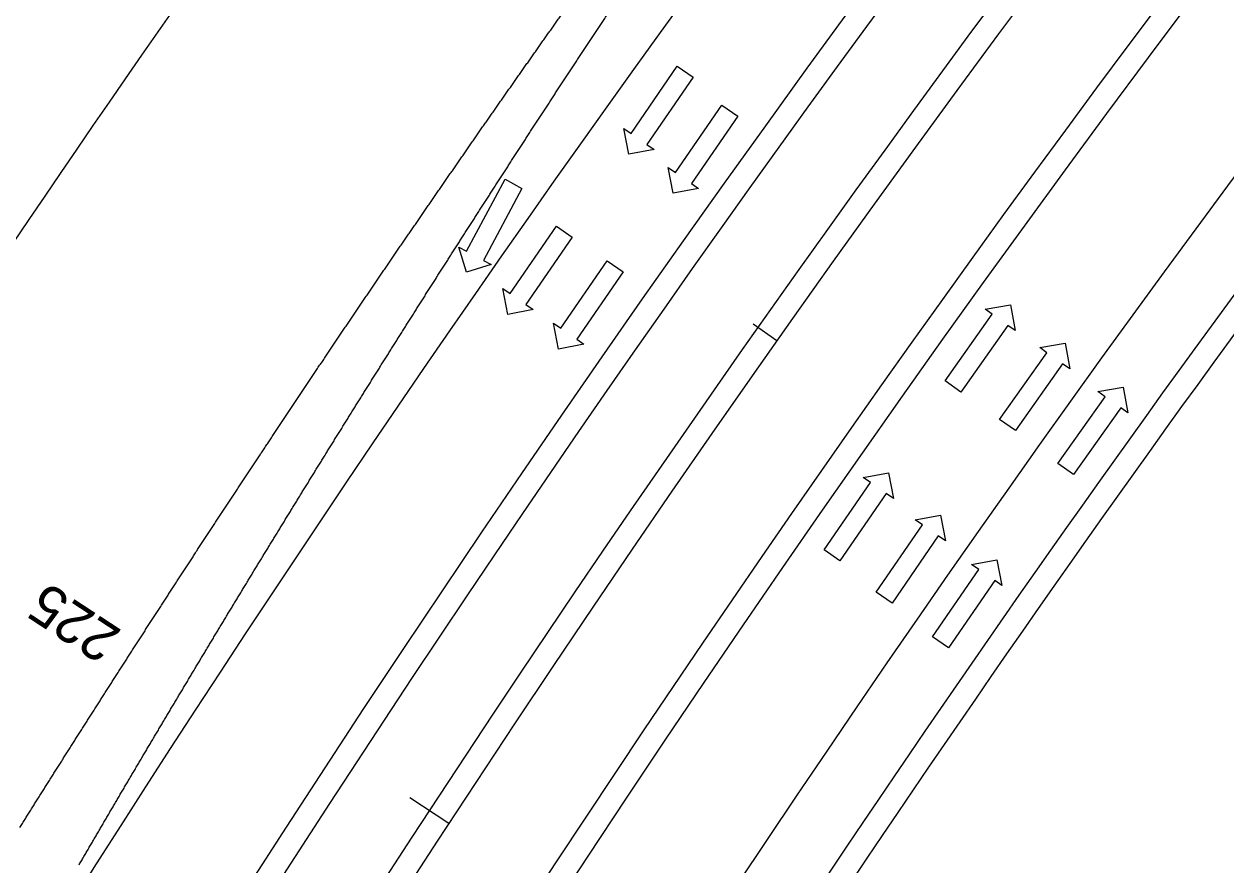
# Model space of a CAD drawing. Extents: x 2389694 to 2405615, y 547005 to 573532.
# Drawn here: x 2400552.8 to 2400758.8, y 569616.1 to 569760.3 of the extents above; entities that cross this region are included whole.
import ezdxf

# ---------------------------------------------------------------- set-up
doc = ezdxf.new("R2010")
doc.units = 0
for name, color, linetype in [('Prop Cable Guiderail Single Face', 7, 'Continuous'), ('Prop Dimension', 7, 'Continuous'), ('Prop EOT', 7, 'Continuous'), ('Prop Horizontal Alignment', 7, 'Continuous'), ('Prop Horizontal Alignment Curve and Spiral Data', 7, 'Continuous'), ('Prop Horizontal Alignment Tick Large', 7, 'Continuous'), ('Prop Horizontal Alignment Tick Small', 7, 'Continuous'), ('Prop Lane Arrow Through CELL', 7, 'Continuous'), ('Prop Lane Lines', 7, 'Continuous')]:
    doc.layers.add(name, color=color, linetype=linetype)

msp = doc.modelspace()

# ---------------------------------------------------------------- linework, layer by layer
at = {"layer": 'Prop Cable Guiderail Single Face'}
msp.add_arc((2403051.7, 568034.46), 2904, 119.41161, 162.0892, dxfattribs=at)
at = {"layer": 'Prop Dimension'}
msp.add_arc((2403051.7, 568034.46), 3017.28, 142.82813, 148.75528, dxfattribs=at)
at = {"layer": 'Prop EOT'}
for radius, start, end in [(2923, 119.41161, 180.94658), (2919, 119.41161, 162.43732), (2881, 119.41161, 165.38993), (2877, 119.41161, 180.94658), (2841, 142.65815, 148.75529), (2837, 142.65815, 148.75529)]:
    msp.add_arc((2403051.7, 568034.46), radius, start, end, dxfattribs=at)
for points in [[(2400619.32, 569725.07), (2400619.79, 569725.75), (2400620.26, 569726.44), (2400620.73, 569727.12), (2400621.2, 569727.8), (2400621.67, 569728.48), (2400622.13, 569729.16), (2400622.61, 569729.85), (2400623.08, 569730.53), (2400623.55, 569731.22), (2400624.02, 569731.9), (2400624.49, 569732.58), (2400624.96, 569733.26), (2400625.43, 569733.94), (2400625.9, 569734.62), (2400626.37, 569735.3), (2400626.84, 569735.98), (2400627.31, 569736.66), (2400627.78, 569737.34), (2400628.26, 569738.03), (2400628.73, 569738.71), (2400629.2, 569739.39), (2400629.67, 569740.07), (2400630.15, 569740.75), (2400630.62, 569741.43), (2400631.09, 569742.11), (2400631.56, 569742.79), (2400632.04, 569743.47), (2400632.51, 569744.15), (2400632.98, 569744.82), (2400633.46, 569745.5), (2400633.93, 569746.19), (2400634.41, 569746.87), (2400634.88, 569747.55), (2400635.36, 569748.22), (2400635.83, 569748.9), (2400636.31, 569749.58), (2400636.78, 569750.26), (2400637.26, 569750.94), (2400637.73, 569751.61), (2400638.21, 569752.29), (2400638.68, 569752.97), (2400639.16, 569753.64), (2400639.63, 569754.32), (2400640.11, 569755.01), (2400640.59, 569755.68), (2400641.07, 569756.36), (2400641.54, 569757.04), (2400642.02, 569757.71), (2400642.5, 569758.39), (2400642.98, 569759.06), (2400643.45, 569759.74), (2400643.93, 569760.42), (2400644.41, 569761.09), (2400644.89, 569761.77), (2400645.36, 569762.44), (2400645.85, 569763.13), (2400646.33, 569763.8), (2400646.81, 569764.48), (2400647.28, 569765.15), (2400647.76, 569765.83), (2400648.24, 569766.5), (2400648.72, 569767.17), (2400649.2, 569767.85), (2400649.68, 569768.52), (2400650.16, 569769.2), (2400650.64, 569769.87), (2400651.12, 569770.54), (2400651.61, 569771.23), (2400652.09, 569771.9), (2400652.57, 569772.57), (2400653.05, 569773.25), (2400653.53, 569773.92), (2400654.02, 569774.59), (2400654.5, 569775.27)], [(2400625.89, 569720.5), (2400626.34, 569721.2), (2400626.78, 569721.9), (2400627.23, 569722.59), (2400627.67, 569723.29), (2400628.12, 569723.98), (2400628.56, 569724.68), (2400629.01, 569725.38), (2400629.46, 569726.08), (2400629.91, 569726.77), (2400630.35, 569727.47), (2400630.8, 569728.16), (2400631.25, 569728.86), (2400631.69, 569729.55), (2400632.14, 569730.25), (2400632.59, 569730.94), (2400633.03, 569731.64), (2400633.48, 569732.33), (2400633.93, 569733.02), (2400634.38, 569733.73), (2400634.83, 569734.42), (2400635.28, 569735.11), (2400635.73, 569735.81), (2400636.18, 569736.5), (2400636.63, 569737.19), (2400637.08, 569737.89), (2400637.52, 569738.58), (2400637.97, 569739.27), (2400638.42, 569739.96), (2400638.87, 569740.66), (2400639.32, 569741.35), (2400639.78, 569742.05), (2400640.23, 569742.74), (2400640.68, 569743.44), (2400641.13, 569744.13), (2400641.58, 569744.82), (2400642.04, 569745.51), (2400642.49, 569746.2), (2400642.94, 569746.9), (2400643.39, 569747.59), (2400643.84, 569748.28), (2400644.29, 569748.97), (2400644.75, 569749.66), (2400645.2, 569750.35), (2400645.66, 569751.05), (2400646.11, 569751.74), (2400646.57, 569752.43), (2400647.02, 569753.12), (2400647.47, 569753.81), (2400647.93, 569754.5), (2400648.38, 569755.19), (2400648.84, 569755.88), (2400649.29, 569756.57), (2400649.74, 569757.26), (2400650.2, 569757.95), (2400650.65, 569758.64), (2400651.12, 569759.34), (2400651.57, 569760.03), (2400652.03, 569760.72), (2400652.48, 569761.41), (2400652.94, 569762.1), (2400653.4, 569762.79), (2400653.85, 569763.48), (2400654.31, 569764.16), (2400654.77, 569764.85), (2400655.22, 569765.54), (2400655.68, 569766.23), (2400656.14, 569766.92), (2400656.6, 569767.61), (2400657.06, 569768.3), (2400657.52, 569768.99), (2400657.98, 569769.68), (2400658.43, 569770.36), (2400658.89, 569771.05), (2400659.35, 569771.74)], [(2400585.2, 569674.17), (2400585.66, 569674.86), (2400586.11, 569675.55), (2400586.56, 569676.24), (2400587.02, 569676.93), (2400587.47, 569677.62), (2400587.93, 569678.31), (2400588.39, 569679.01), (2400588.84, 569679.71), (2400589.3, 569680.4), (2400589.75, 569681.09), (2400590.21, 569681.78), (2400590.66, 569682.47), (2400591.12, 569683.16), (2400591.58, 569683.85), (2400592.03, 569684.54), (2400592.49, 569685.23), (2400592.95, 569685.92), (2400593.4, 569686.61), (2400593.87, 569687.31), (2400594.32, 569688), (2400594.78, 569688.68), (2400595.24, 569689.37), (2400595.7, 569690.06), (2400596.15, 569690.75), (2400596.61, 569691.44), (2400597.07, 569692.13), (2400597.53, 569692.82), (2400597.99, 569693.51), (2400598.45, 569694.19), (2400598.91, 569694.88), (2400599.37, 569695.58), (2400599.83, 569696.27), (2400600.29, 569696.96), (2400600.75, 569697.64), (2400601.21, 569698.33), (2400601.67, 569699.02), (2400602.13, 569699.71), (2400602.59, 569700.39), (2400603.05, 569701.08), (2400603.51, 569701.77), (2400603.98, 569702.45), (2400604.44, 569703.14), (2400604.9, 569703.83), (2400605.37, 569704.52), (2400605.83, 569705.21), (2400606.29, 569705.89), (2400606.75, 569706.58), (2400607.22, 569707.27), (2400607.68, 569707.95), (2400608.14, 569708.64), (2400608.61, 569709.32), (2400609.07, 569710.01), (2400609.53, 569710.69), (2400610, 569711.38), (2400610.46, 569712.06), (2400610.93, 569712.76), (2400611.39, 569713.44), (2400611.86, 569714.13), (2400612.32, 569714.81), (2400612.79, 569715.49), (2400613.25, 569716.18), (2400613.72, 569716.86), (2400614.18, 569717.55), (2400614.65, 569718.23), (2400615.12, 569718.91), (2400615.58, 569719.6), (2400616.05, 569720.28), (2400616.52, 569720.97), (2400616.99, 569721.66), (2400617.45, 569722.34), (2400617.92, 569723.02), (2400618.39, 569723.71), (2400618.86, 569724.39), (2400619.32, 569725.07)], [(2400593.53, 569668.63), (2400593.96, 569669.33), (2400594.39, 569670.04), (2400594.82, 569670.74), (2400595.25, 569671.45), (2400595.68, 569672.15), (2400596.11, 569672.85), (2400596.55, 569673.57), (2400596.98, 569674.27), (2400597.41, 569674.97), (2400597.84, 569675.68), (2400598.27, 569676.38), (2400598.7, 569677.08), (2400599.14, 569677.79), (2400599.57, 569678.49), (2400600, 569679.19), (2400600.43, 569679.9), (2400600.87, 569680.6), (2400601.3, 569681.3), (2400601.74, 569682.01), (2400602.17, 569682.71), (2400602.6, 569683.42), (2400603.04, 569684.12), (2400603.47, 569684.82), (2400603.91, 569685.52), (2400604.34, 569686.22), (2400604.77, 569686.93), (2400605.21, 569687.63), (2400605.64, 569688.33), (2400606.08, 569689.03), (2400606.52, 569689.73), (2400606.96, 569690.44), (2400607.39, 569691.14), (2400607.83, 569691.84), (2400608.26, 569692.54), (2400608.7, 569693.24), (2400609.14, 569693.95), (2400609.57, 569694.65), (2400610.01, 569695.35), (2400610.45, 569696.05), (2400610.89, 569696.75), (2400611.32, 569697.45), (2400611.76, 569698.15), (2400612.2, 569698.85), (2400612.64, 569699.55), (2400613.08, 569700.25), (2400613.52, 569700.95), (2400613.96, 569701.65), (2400614.4, 569702.35), (2400614.84, 569703.05), (2400615.28, 569703.75), (2400615.72, 569704.45), (2400616.16, 569705.15), (2400616.6, 569705.84), (2400617.04, 569706.54), (2400617.48, 569707.24), (2400617.92, 569707.95), (2400618.36, 569708.65), (2400618.8, 569709.34), (2400619.25, 569710.04), (2400619.69, 569710.74), (2400620.13, 569711.44), (2400620.57, 569712.14), (2400621.01, 569712.83), (2400621.45, 569713.53), (2400621.9, 569714.23), (2400622.34, 569714.92), (2400622.78, 569715.62), (2400623.23, 569716.33), (2400623.67, 569717.02), (2400624.12, 569717.72), (2400624.56, 569718.42), (2400625.01, 569719.11), (2400625.45, 569719.81), (2400625.89, 569720.5)], [(2400552.15, 569622.57), (2400552.58, 569623.27), (2400553.02, 569623.97), (2400553.46, 569624.68), (2400553.9, 569625.38), (2400554.34, 569626.08), (2400554.78, 569626.78), (2400555.23, 569627.49), (2400555.67, 569628.19), (2400556.11, 569628.89), (2400556.55, 569629.59), (2400556.99, 569630.29), (2400557.43, 569630.99), (2400557.87, 569631.68), (2400558.32, 569632.38), (2400558.76, 569633.08), (2400559.2, 569633.78), (2400559.64, 569634.48), (2400560.09, 569635.18), (2400560.53, 569635.89), (2400560.98, 569636.59), (2400561.42, 569637.29), (2400561.86, 569637.98), (2400562.31, 569638.68), (2400562.75, 569639.38), (2400563.19, 569640.08), (2400563.64, 569640.78), (2400564.08, 569641.47), (2400564.53, 569642.17), (2400564.97, 569642.87), (2400565.42, 569643.57), (2400565.87, 569644.27), (2400566.31, 569644.97), (2400566.76, 569645.67), (2400567.2, 569646.36), (2400567.65, 569647.06), (2400568.09, 569647.76), (2400568.54, 569648.45), (2400568.99, 569649.15), (2400569.43, 569649.85), (2400569.88, 569650.54), (2400570.33, 569651.24), (2400570.77, 569651.93), (2400571.22, 569652.63), (2400571.67, 569653.33), (2400572.12, 569654.03), (2400572.57, 569654.73), (2400573.02, 569655.42), (2400573.47, 569656.12), (2400573.91, 569656.81), (2400574.36, 569657.51), (2400574.81, 569658.2), (2400575.26, 569658.9), (2400575.71, 569659.59), (2400576.16, 569660.29), (2400576.61, 569660.98), (2400577.07, 569661.68), (2400577.52, 569662.38), (2400577.97, 569663.07), (2400578.42, 569663.76), (2400578.87, 569664.46), (2400579.32, 569665.15), (2400579.77, 569665.85), (2400580.22, 569666.54), (2400580.67, 569667.23), (2400581.12, 569667.92), (2400581.58, 569668.62), (2400582.03, 569669.31), (2400582.49, 569670.01), (2400582.94, 569670.7), (2400583.39, 569671.4), (2400583.84, 569672.09), (2400584.3, 569672.78), (2400584.75, 569673.47), (2400585.2, 569674.17)], [(2400562.27, 569616.14), (2400562.69, 569616.85), (2400563.1, 569617.56), (2400563.52, 569618.28), (2400563.93, 569618.99), (2400564.35, 569619.7), (2400564.76, 569620.41), (2400565.19, 569621.13), (2400565.6, 569621.84), (2400566.02, 569622.56), (2400566.43, 569623.27), (2400566.85, 569623.98), (2400567.27, 569624.69), (2400567.68, 569625.4), (2400568.1, 569626.11), (2400568.52, 569626.82), (2400568.94, 569627.54), (2400569.35, 569628.25), (2400569.77, 569628.96), (2400570.2, 569629.68), (2400570.61, 569630.39), (2400571.03, 569631.1), (2400571.45, 569631.81), (2400571.87, 569632.52), (2400572.29, 569633.23), (2400572.71, 569633.94), (2400573.13, 569634.65), (2400573.55, 569635.36), (2400573.97, 569636.07), (2400574.39, 569636.78), (2400574.81, 569637.49), (2400575.23, 569638.2), (2400575.66, 569638.91), (2400576.08, 569639.62), (2400576.5, 569640.33), (2400576.92, 569641.04), (2400577.34, 569641.75), (2400577.76, 569642.46), (2400578.19, 569643.17), (2400578.61, 569643.88), (2400579.03, 569644.58), (2400579.45, 569645.29), (2400579.88, 569646), (2400580.3, 569646.71), (2400580.73, 569647.43), (2400581.15, 569648.13), (2400581.57, 569648.84), (2400582, 569649.55), (2400582.42, 569650.26), (2400582.85, 569650.96), (2400583.27, 569651.67), (2400583.7, 569652.38), (2400584.12, 569653.09), (2400584.55, 569653.79), (2400584.97, 569654.5), (2400585.4, 569655.21), (2400585.83, 569655.92), (2400586.25, 569656.63), (2400586.68, 569657.33), (2400587.11, 569658.04), (2400587.53, 569658.75), (2400587.96, 569659.45), (2400588.39, 569660.16), (2400588.81, 569660.86), (2400589.24, 569661.57), (2400589.67, 569662.28), (2400590.1, 569662.98), (2400590.52, 569663.69), (2400590.96, 569664.4), (2400591.39, 569665.11), (2400591.81, 569665.81), (2400592.24, 569666.52), (2400592.67, 569667.22), (2400593.1, 569667.92), (2400593.53, 569668.63)]]:
    msp.add_spline(points, degree=3, dxfattribs=at)
at = {"layer": 'Prop Horizontal Alignment'}
msp.add_arc((2403051.7, 568034.46), 2900, 119.41161, 180.94658, dxfattribs=at)
at = {"layer": 'Prop Horizontal Alignment Tick Large'}
msp.add_line((2400625.65, 569623.26), (2400618.96, 569627.64), dxfattribs=at)
at = {"layer": 'Prop Horizontal Alignment Tick Small'}
msp.add_line((2400681.87, 569705.95), (2400677.78, 569708.84), dxfattribs=at)
at = {"layer": 'Prop Lane Arrow Through CELL'}
for p, q in [((2400656.87, 569741.5), (2400664.8, 569753.04)), ((2400664.8, 569753.04), (2400667.52, 569751.17)), ((2400667.52, 569751.17), (2400659.59, 569739.63)), ((2400664.49, 569734.81), (2400672.43, 569746.34)), ((2400672.43, 569746.34), (2400675.15, 569744.47)), ((2400675.15, 569744.47), (2400667.21, 569732.94)), ((2400656.48, 569737.94), (2400655.63, 569742.35)), ((2400655.63, 569742.35), (2400656.87, 569741.5)), ((2400660.82, 569738.78), (2400656.48, 569737.94)), ((2400659.59, 569739.63), (2400660.82, 569738.78)), ((2400664.11, 569731.25), (2400663.26, 569735.66)), ((2400663.26, 569735.66), (2400664.49, 569734.81)), ((2400628.66, 569721.31), (2400635.28, 569733.65)), ((2400638.18, 569732.09), (2400631.57, 569719.75)), ((2400635.28, 569733.65), (2400638.18, 569732.09)), ((2400668.45, 569732.09), (2400664.11, 569731.25)), ((2400667.21, 569732.94), (2400668.45, 569732.09)), ((2400636.15, 569714.06), (2400644.09, 569725.6)), ((2400646.81, 569723.73), (2400638.87, 569712.19)), ((2400644.09, 569725.6), (2400646.81, 569723.73)), ((2400628.67, 569717.73), (2400627.34, 569722.02)), ((2400627.34, 569722.02), (2400628.66, 569721.31)), ((2400631.57, 569719.75), (2400632.89, 569719.04)), ((2400644.84, 569708.12), (2400652.78, 569719.66)), ((2400652.78, 569719.66), (2400655.5, 569717.79)), ((2400632.89, 569719.04), (2400628.67, 569717.73)), ((2400655.5, 569717.79), (2400647.56, 569706.25)), ((2400635.77, 569710.5), (2400634.92, 569714.91)), ((2400634.92, 569714.91), (2400636.15, 569714.06)), ((2400640.11, 569711.34), (2400635.77, 569710.5)), ((2400638.87, 569712.19), (2400640.11, 569711.34)), ((2400717.55, 569711.38), (2400721.9, 569712.16)), ((2400718.78, 569710.52), (2400717.55, 569711.38)), ((2400721.9, 569712.16), (2400722.69, 569707.74)), ((2400710.68, 569699.1), (2400718.78, 569710.52)), ((2400644.46, 569704.56), (2400643.61, 569708.97)), ((2400643.61, 569708.97), (2400644.84, 569708.12)), ((2400721.47, 569708.61), (2400713.37, 569697.19)), ((2400722.69, 569707.74), (2400721.47, 569708.61)), ((2400648.8, 569705.4), (2400644.46, 569704.56)), ((2400647.56, 569706.25), (2400648.8, 569705.4)), ((2400726.92, 569704.8), (2400731.27, 569705.57)), ((2400731.27, 569705.57), (2400732.06, 569701.15)), ((2400720.04, 569692.51), (2400728.14, 569703.93)), ((2400728.14, 569703.93), (2400726.92, 569704.8)), ((2400730.83, 569702.02), (2400722.74, 569690.6)), ((2400732.06, 569701.15), (2400730.83, 569702.02)), ((2400713.37, 569697.19), (2400710.68, 569699.1)), ((2400736.88, 569697.26), (2400741.23, 569698.03)), ((2400738.11, 569696.39), (2400736.88, 569697.26)), ((2400741.23, 569698.03), (2400742.02, 569693.61)), ((2400730.02, 569684.96), (2400738.11, 569696.39)), ((2400740.8, 569694.48), (2400732.71, 569683.06)), ((2400742.02, 569693.61), (2400740.8, 569694.48)), ((2400722.74, 569690.6), (2400720.04, 569692.51)), ((2400732.71, 569683.06), (2400730.02, 569684.96)), ((2400696.66, 569682.53), (2400701, 569683.37)), ((2400697.9, 569681.68), (2400696.66, 569682.53)), ((2400701, 569683.37), (2400701.85, 569678.96)), ((2400689.97, 569670.14), (2400697.9, 569681.68)), ((2400700.62, 569679.81), (2400692.68, 569668.27)), ((2400701.85, 569678.96), (2400700.62, 569679.81)), ((2400698.88, 569662.88), (2400706.81, 569674.42)), ((2400705.58, 569675.27), (2400709.92, 569676.1)), ((2400706.81, 569674.42), (2400705.58, 569675.27)), ((2400709.92, 569676.1), (2400710.77, 569671.7)), ((2400709.53, 569672.55), (2400701.6, 569661.01)), ((2400710.77, 569671.7), (2400709.53, 569672.55)), ((2400692.68, 569668.27), (2400689.97, 569670.14)), ((2400715.24, 569667.61), (2400719.58, 569668.44)), ((2400719.58, 569668.44), (2400720.43, 569664.04)), ((2400708.55, 569655.22), (2400716.48, 569666.76)), ((2400716.48, 569666.76), (2400715.24, 569667.61)), ((2400719.2, 569664.89), (2400711.26, 569653.35)), ((2400720.43, 569664.04), (2400719.2, 569664.89)), ((2400701.6, 569661.01), (2400698.88, 569662.88)), ((2400711.26, 569653.35), (2400708.55, 569655.22))]:
    msp.add_line(p, q, dxfattribs=at)
at = {"layer": 'Prop Lane Lines'}
for radius, start, end in [(2947, 129.29029, 148.75528), (2853, 131.16509, 154.68244)]:
    msp.add_arc((2403051.7, 568034.46), radius, start, end, dxfattribs=at)

# ---------------------------------------------------------------- texts
at = {"layer": 'Prop Horizontal Alignment Curve and Spiral Data'}
msp.add_text('225', height=7, rotation=146.7796, dxfattribs=at).set_placement((2400569.81, 569656.23))

doc.saveas('drawing.dxf')
